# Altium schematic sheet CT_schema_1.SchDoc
size 470 x 258 mm
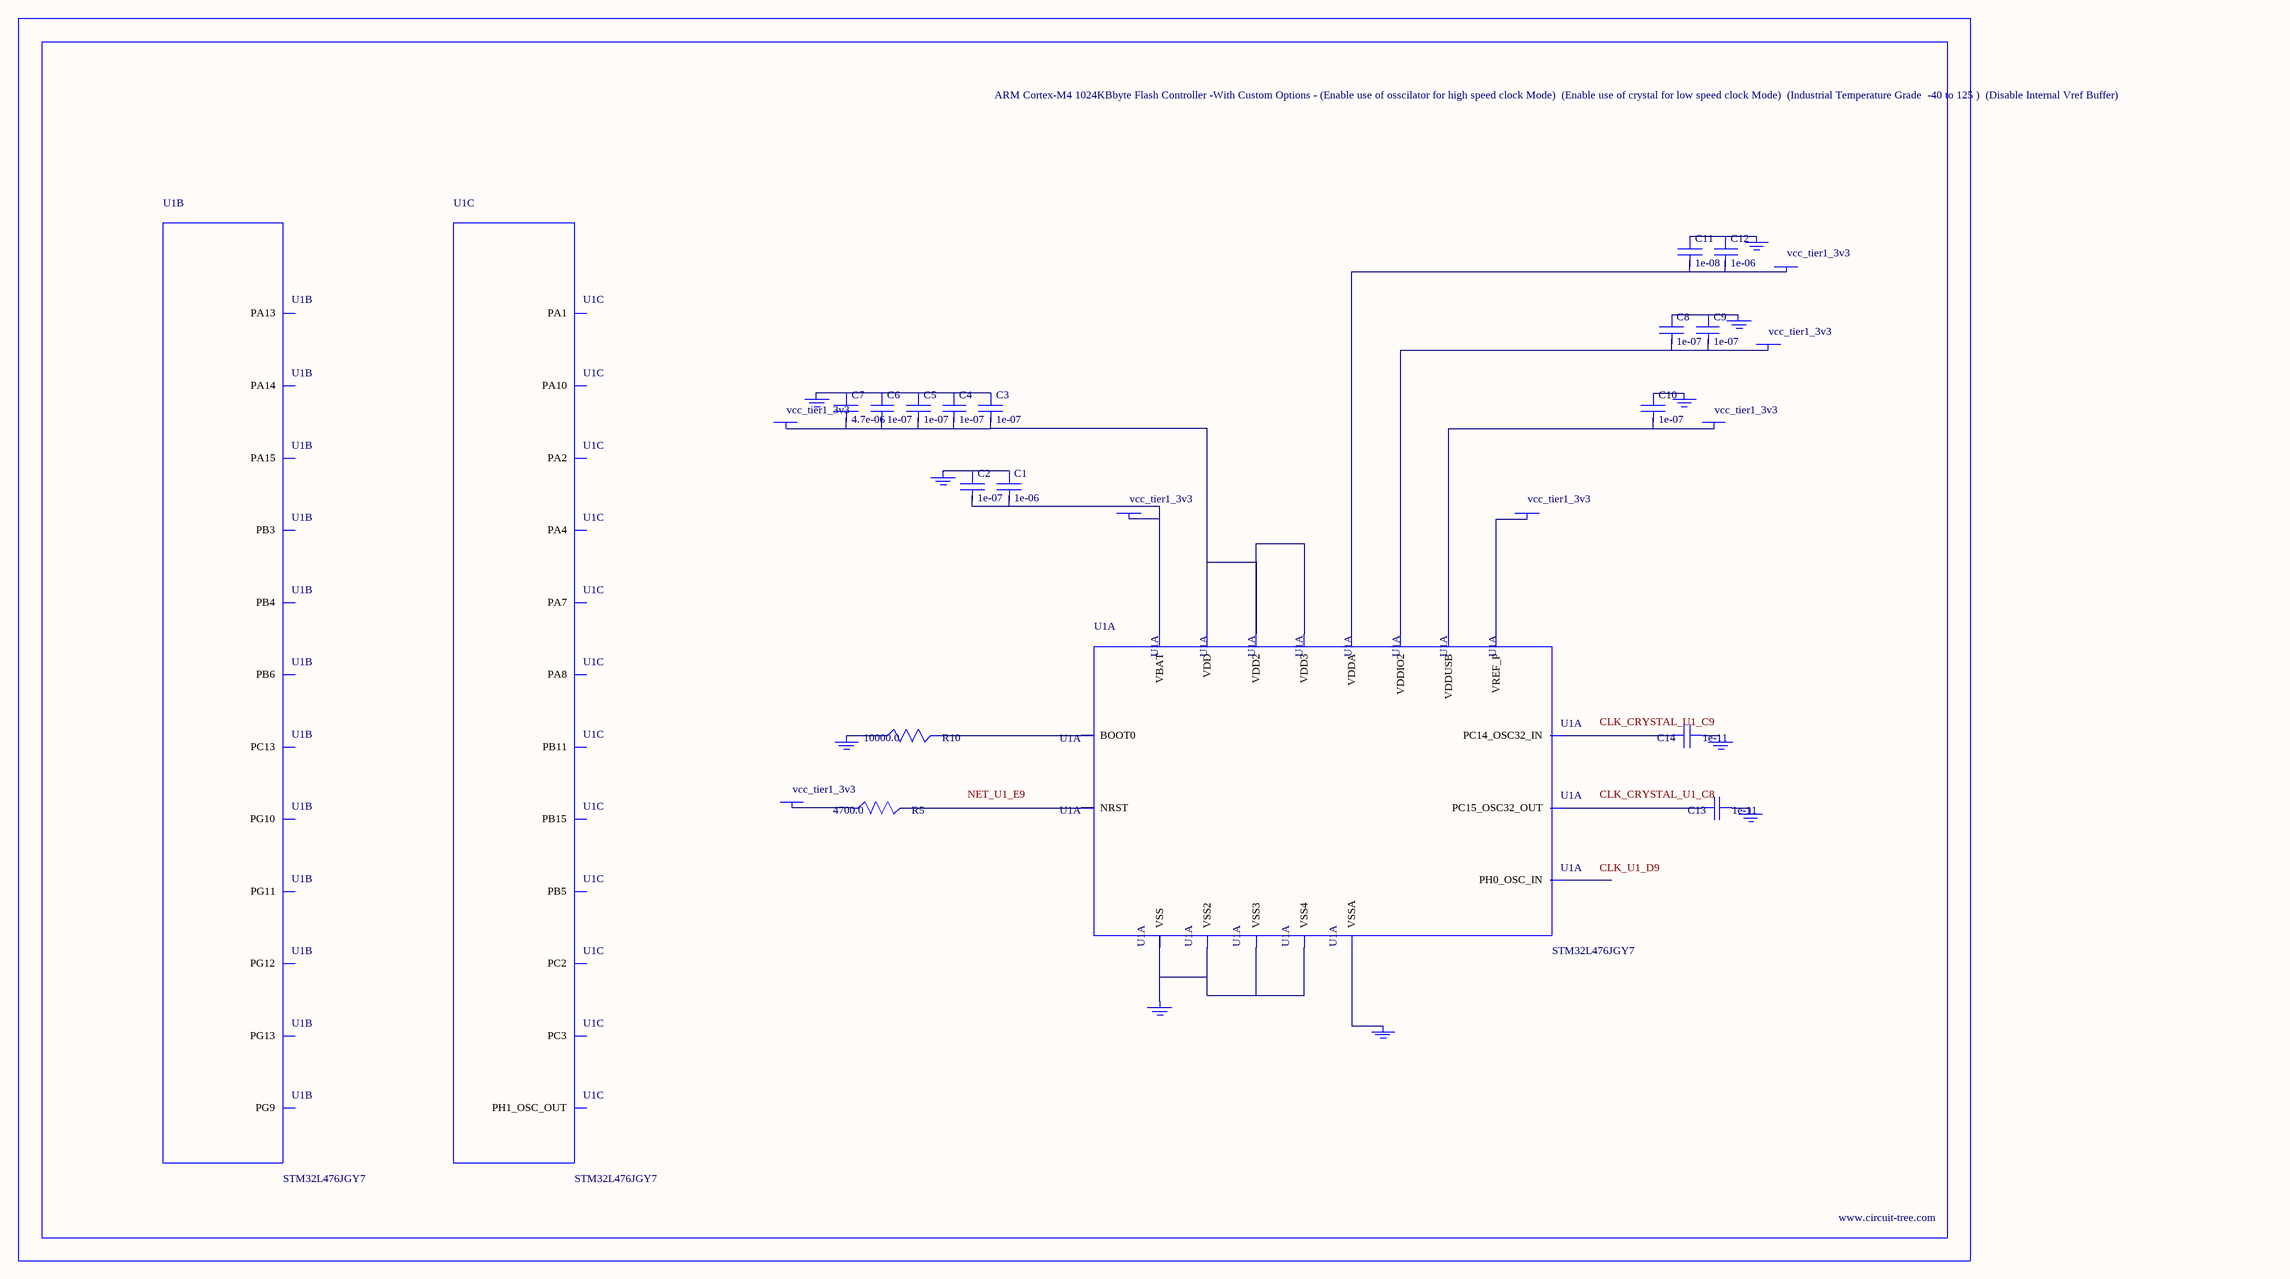
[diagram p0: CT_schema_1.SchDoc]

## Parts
BORDER0  (no value)
C1  1e-06  [C0603]
C2  1e-07  [C0603]
C3  1e-07  [C0603]
C4  1e-07  [C0603]
C5  1e-07  [C0603]
C6  1e-07  [C0603]
C7  4.7e-06  [C0603]
C8  1e-07  [C0603]
C9  1e-07  [C0603]
C10  1e-07  [C0603]
C11  1e-08  [C0603]
C12  1e-06  [C0603]
C13  1e-11  [C0402]
C14  1e-11  [C0402]
GND_INSTANCE_0_0  (no value)
GND_INSTANCE_0_1  (no value)
GND_INSTANCE_0_2  (no value)
GND_INSTANCE_0_3  (no value)
GND_INSTANCE_0_4  (no value)
GND_INSTANCE_0_5  (no value)
GND_INSTANCE_0_6  (no value)
GND_INSTANCE_0_7  (no value)
GND_INSTANCE_0_8  (no value)
GND_INSTANCE_0_9  (no value)
POWER_INSTANCE_0_0  vcc_tier1_3v3
POWER_INSTANCE_0_1  vcc_tier1_3v3
POWER_INSTANCE_0_2  vcc_tier1_3v3
POWER_INSTANCE_0_3  vcc_tier1_3v3
POWER_INSTANCE_0_4  vcc_tier1_3v3
POWER_INSTANCE_0_5  vcc_tier1_3v3
POWER_INSTANCE_0_6  vcc_tier1_3v3
R5  4700.0  [R0603]
R10  10000.0  [R0603]
U1  STM32L476JGY7  [WLCSP72]  (parts A,B,C of 8)

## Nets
NetC1_1: C1.1 C2.1 GND_INSTANCE_0_0.0(GND)
NetC1_2: C1.2 C2.2 POWER_INSTANCE_0_0.0(PWR) U1.B9(VBAT)
NetC3_1: C3.1 C4.1 C5.1 C6.1 C7.1 GND_INSTANCE_0_1.0(GND)
NetC3_2: C3.2 C4.2 C5.2 C6.2 C7.2 POWER_INSTANCE_0_1.0(PWR) U1.A9(VDD) U1.J1(VDD2) U1.J8(VDD3)
NetC8_1: C8.1 C9.1 GND_INSTANCE_0_2.0(GND)
NetC8_2: C8.2 C9.2 POWER_INSTANCE_0_2.0(PWR) U1.B6(VDDIO2)
NetC10_1: C10.1 GND_INSTANCE_0_4.0(GND)
NetC10_2: C10.2 POWER_INSTANCE_0_3.0(PWR) U1.A1(VDDUSB)
NetC11_1: C11.1 C12.1 GND_INSTANCE_0_5.0(GND)
NetC11_2: C11.2 C12.2 POWER_INSTANCE_0_4.0(PWR) U1.H9(VDDA)
NetC13_1: C13.1 GND_INSTANCE_0_6.0(GND)
NetC13_2: C13.2 U1.C8(PC15_OSC32_OUT)
NetC14_1: C14.1 GND_INSTANCE_0_7.0(GND)
NetC14_2: C14.2 U1.C9(PC14_OSC32_IN)
NetGND_INSTANCE_0_3_0: GND_INSTANCE_0_3.0(GND) R10.1
NetGND_INSTANCE_0_8_0: GND_INSTANCE_0_8.0(GND) U1.G9(VSSA)
NetGND_INSTANCE_0_9_0: GND_INSTANCE_0_9.0(GND) U1.A8(VSS) U1.B1(VSS2) U1.J2(VSS3) U1.J9(VSS4)
NetPOWER_INSTANCE_0_5_0: POWER_INSTANCE_0_5.0(PWR) U1.G8(VREF_P)
NetPOWER_INSTANCE_0_6_0: POWER_INSTANCE_0_6.0(PWR) R5.1
NetR5_2: R5.2 U1.E9(NRST)
NetR10_2: R10.2 U1.D7(BOOT0)

Not connected (* = marked no-connect by the designer): U1 A2(PA15) A4(PG9) A6(PB3) B2(PA14) B4(PG10) B5(PG13) B7(PB6) B8(PC13) C2(PA13) C4(PG11) C5(PG12) C6(PB4) C7(PB5) D2(PA10) D8(PH1_OSC_OUT) D9(PH0_OSC_IN) E2(PA8) F7(PC2) G1(PB15) G3(PB11) G4(PA1) G5(PA4) G6(PA2) G7(PC3) H4(PA7)

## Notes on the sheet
- Labels drawn without touching a wire or pin: CLK_CRYSTAL_U1_C8, CLK_CRYSTAL_U1_C9, CLK_U1_D9, NET_U1_E9

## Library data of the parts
BORDER0 = BORDER_PAGE0
C1 C12 = C0603C105K3RACTU
C2-C6 C8-C10 = 06035C104K4Z2A
C7 = GRM188R6YA475KE15D
C11 = 06035C103K4Z2A
C13 C14 = C0402C100K3GACTU
GND_INSTANCE_0_0-GND_INSTANCE_0_9 = GND
POWER_INSTANCE_0_0-POWER_INSTANCE_0_6 = PWR
R5 = RC0603JR-074K7L
R10 = RC0603JR-0710KL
